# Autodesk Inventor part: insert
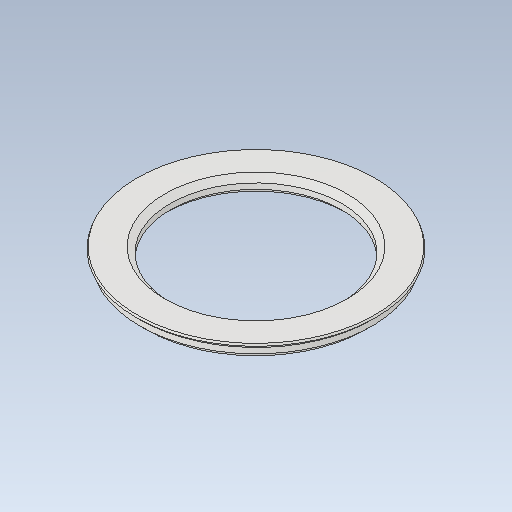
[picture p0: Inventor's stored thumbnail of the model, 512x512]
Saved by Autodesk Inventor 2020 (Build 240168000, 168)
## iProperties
Created: 2015-11
Part Number: insert
Material: Ogólny
Document SubType Name: Modeling
Designer: Tomasz
Density: 1 g/cm^3
Appearance: Domyślna
Sending System: SolidWorks 2017
Last Author: Tomasz
Last Saved: 2017-09-26
Author: Tomasz
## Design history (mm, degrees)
feature "Imported1"
node "Bryła1"
